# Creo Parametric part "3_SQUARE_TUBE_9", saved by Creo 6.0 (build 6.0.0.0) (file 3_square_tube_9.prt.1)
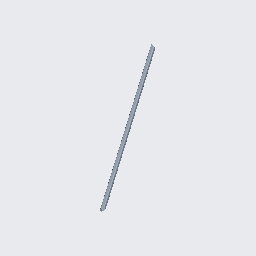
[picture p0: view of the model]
Units: Custom; MM, KILOGRAM, SECS
Materials in the file: STEEL

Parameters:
  BUW_NAME = "SQUARE TUBE"
  BUW_TYPE = "DIN EN 10219"
  BUW_SIZE = "25x25x3.0"
  BUW_LENGTH_STR = "1235"
  PTC_MATERIAL_NAME = "STEEL"
  BUW_PROFIL_TYPE = "square_tube"
  BUW_PROFILE_PATH = "parts//profiles/steel_beams_mm/"
  BUW_PROFILE_NAME_LANG = "SQUARE TUBE"
  BUW_TAB_SEL_INFO = "-2 TYPE DIN_EN_10219-1997 SIZE_DINEN_10219 25x25x3.0"
  NAMING = "SQUARE TUBE"
  DESIGNATION = "DIN EN 10219 25x25x3.0 x 1235"
  PROFIL_RASTER_POS = "X_0"
  BUW_OBJECT_ROLE = "PROFIL_SYSTEM_BORE_END_POINTS"
  PRO_UNIT_SYS = "Custom"

Other parameters: BUW_LENGTH, LENGTH, BUW_LENGTH_Z_MIN_PARAM, D8, D93, D94, d26, d8, d93, d94, d98, D98, SHEAR_MODULUS, THERM_EXPANSION_REF_TEMPERATURE, STRUCTURAL_DAMPING_COEFFICIENT, STRESS_LIMIT_FOR_TENSION, STRESS_LIMIT_FOR_COMPRESSION, STRESS_LIMIT_FOR_SHEAR, EMISSIVITY

Created from: SQUARE_TUBE.PRT

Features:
  1. datum plane "YZ"
  2. datum plane "XZ"
  3. datum plane "XY"
  4. coordinate system
  5. coordinate system
  6. coordinate system
  7. coordinate system
  8. datum plane "DTM3"
  9. datum plane "DTM4"
  10. datum plane "DTM5"
  11. protrusion
  12. round
  13. round
  14. datum axis
  15. datum point "PNT0"
  16. datum point

Other named items: PROFIL_CUT_QUILT, PROFILE_LENGTH_DIM, CONTACT_SURF_3, CONTACT_SURF_2, CONTACT_SURF_1, CONTACT_SURF_0, E, START_SURFACE, END_SURFACE, SIDE_SURF_3, SIDE_SURF_0, SIDE_SURF_1, SIDE_SURF_2, EDGE_7_S, EDGE_7_E, EDGE_1_S, EDGE_1_E, EDGE_3_S, EDGE_3_E, EDGE_5_S, EDGE_5_E, EDGE_6_S, EDGE_4_S, EDGE_2_S, EDGE_0_S, EDGE_6_E, EDGE_4_E, EDGE_2_E, EDGE_0_E, CS0, CS_S, CS_E, CS3

Named dimensions: X_ROT_S, Y_ROT_S, Z_OFF_S, X_ROT_E, Y_ROT_E, Z_OFF_E, PC_L, BUW_LENGTH_Z_MIN, BUW_LENGTH_DIM

Layers: 00_PROFIL_DATUM, 00_PROFIL_DRW_HIDE, 00_PROFIL_END_CSYS, 00_PROFIL_GEOMETRY, 00_PROFIL_QUILT, 00_PROFIL_SIZE_NOTE

Surfaces: 16 plane, 12 cylinder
